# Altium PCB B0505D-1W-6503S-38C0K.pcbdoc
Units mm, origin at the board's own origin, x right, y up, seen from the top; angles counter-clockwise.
Board outline 33 x 16 mm, 2 copper layers (Top Layer, Bottom Layer), stack 0.78 mm thick; 15 components, 9 nets, 38 pads, 14 vias.
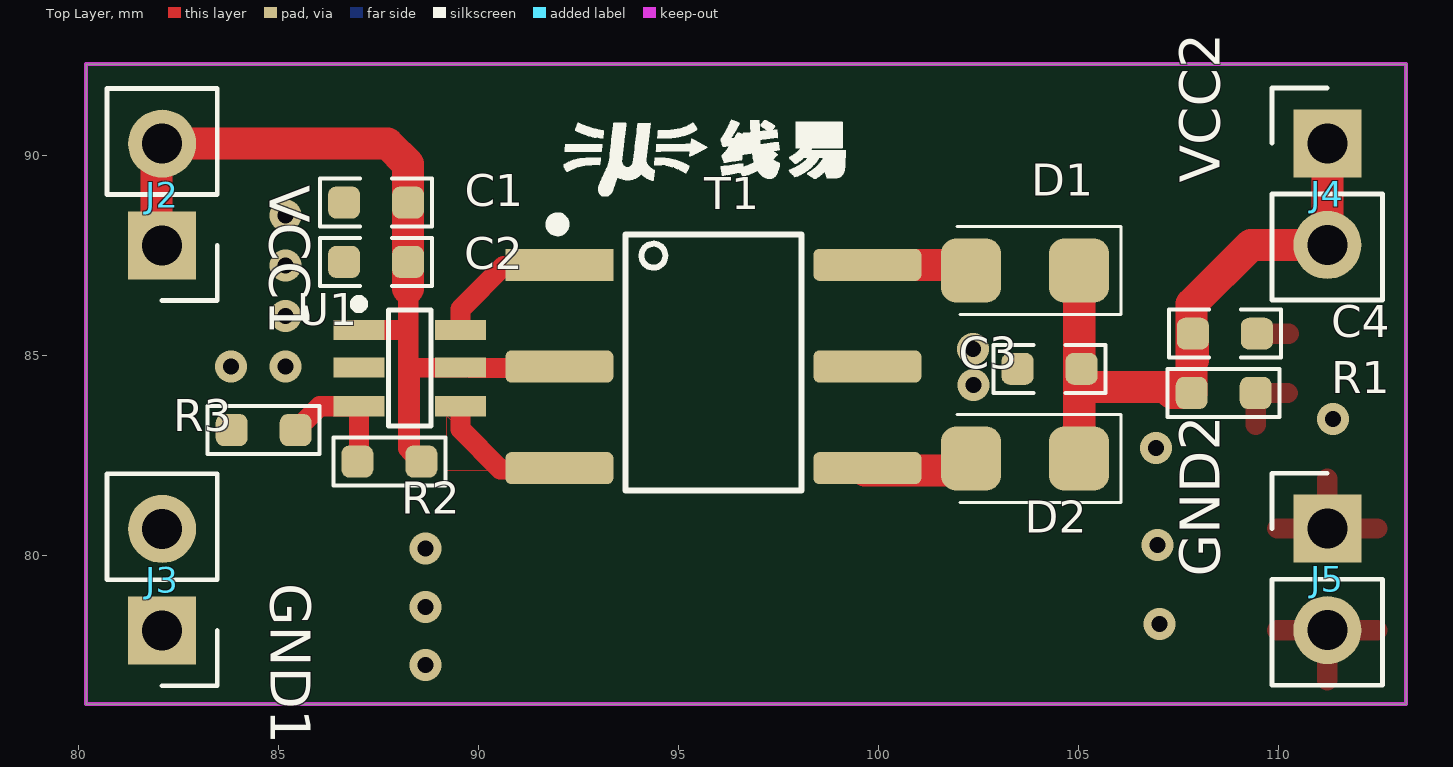
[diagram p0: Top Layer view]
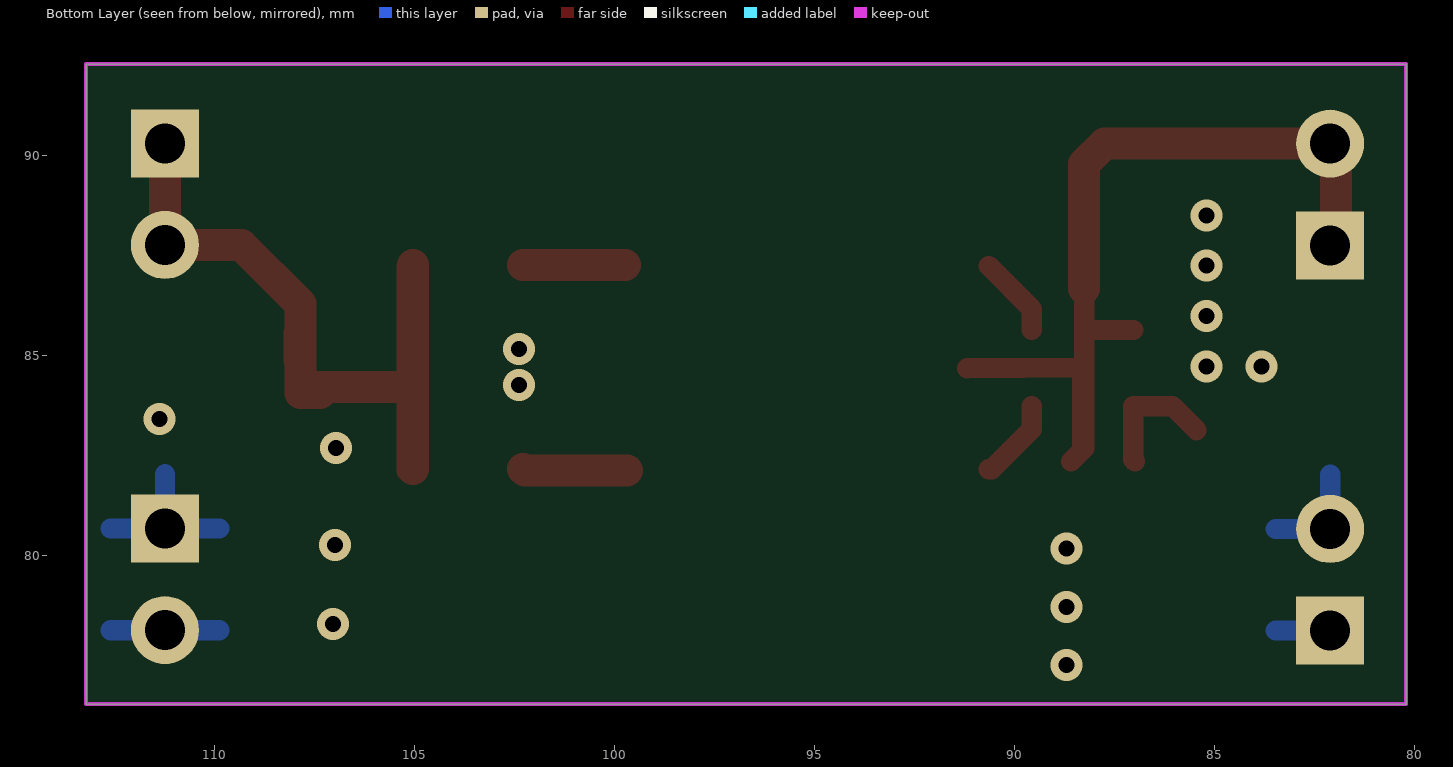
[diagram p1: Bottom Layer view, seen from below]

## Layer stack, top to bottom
Top Solder Mask Layer: solder mask 0.01, Dk 0
Top Layer: signal copper 0.035
dielectric 1: surface 0.71, FR4, Dk 4.5
Bottom Layer: signal copper 0.035
Bottom Solder Mask Layer: solder mask 0.01, Dk 0

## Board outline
80.2,92.284 113.2,92.284 113.2,76.284 80.2,76.284

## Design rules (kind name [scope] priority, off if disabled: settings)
BoardOutlineClearance default [All] p0: genericclearance=0.254 ignorepadtopadclearanceinfootprint=FALSE except(0: Arc-SplitContinuation Track-SplitContinuation SMDPad-SplitContinuation THPad-SplitContinuation Via-SplitContinuation Fill-SplitContinuation Poly-SplitContinuation Region-SplitContinuation Text-SplitContinuation)
BoardOutlineClearance safeClearance [All] p0: genericclearance=0.254 ignorepadtopadclearanceinfootprint=FALSE except(0: Arc-SplitContinuation Track-SplitContinuation SMDPad-SplitContinuation THPad-SplitContinuation Via-SplitContinuation Fill-SplitContinuation Poly-SplitContinuation Region-SplitContinuation Text-SplitContinuation)
BoardOutlineClearance otherClearance [All] p0: genericclearance=0.254 ignorepadtopadclearanceinfootprint=FALSE except(0: Arc-SplitContinuation Track-SplitContinuation SMDPad-SplitContinuation THPad-SplitContinuation Via-SplitContinuation Fill-SplitContinuation Poly-SplitContinuation Region-SplitContinuation Text-SplitContinuation)
Clearance default [All] p1: gap=0.178 ignorepadtopadclearanceinfootprint=FALSE
Clearance safeClearance [All] p1: gap=0.178 ignorepadtopadclearanceinfootprint=FALSE
Clearance otherClearance [All] p1: gap=0.178 ignorepadtopadclearanceinfootprint=FALSE
DiffPairsRouting differentialPair [All] p1: maxuncoupledlength=10 minlimit=5 maxlimit=Infinity mostfreqgap=6 toplayer_minwidth=5 toplayer_prefwidth=100 toplayer_maxwidth=100 bottomlayer_minwidth=5 bottomlayer_prefwidth=100 bottomlayer_maxwidth=100
PasteMaskExpansion pasteMaskExpansion [All] p1: expansion=0
PlaneConnect innerPlane [All] p1: planeconnectstyle=Relief reliefexpansion=0.508 reliefentries=4 reliefconductorwidth=0.254 reliefairgap=0.254
PolygonConnect copper0 [All] p1: connectstyle=Relief reliefentries=4 reliefconductorwidth=0 polygonreliefangle="90 Angle" airgapwidth=0
PolygonConnect copper1 [All] p1: connectstyle=Relief reliefentries=4 reliefconductorwidth=20 polygonreliefangle="90 Angle" airgapwidth=15.748
PolygonConnect copper2 [All] p1: connectstyle=Relief reliefentries=4 reliefconductorwidth=20 polygonreliefangle="90 Angle" airgapwidth=20
RoutingVias viaSize [All] p1: viastyle="Through Hole" holewidth=24 minholewidth=11.811 maxholewidth=393.7 width=24 minwidth=11.811 maxwidth=393.7
SolderMaskExpansion solderMaskExpansion [All] p1: useseparateexpansions=TRUE expansion=2 expansionbottom=2
Width copperThickness1oz [All] p1: maxlimit=100 minlimit=5 preferedwidth=10

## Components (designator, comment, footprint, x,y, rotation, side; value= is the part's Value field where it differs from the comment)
C1 "10uF" C0603 87.45,88.824 r0 top
C2 "NC" C0603 87.45,87.338 r0 top
C3 "10uF" C0603 104.288,84.668 r0 top
C4 "100nF" C0603 108.67,85.544 r180 top
D1 "B5819WS" SOD-323_L1.8-W1.3-LS2.5-RD 103.674,87.124 r180 top
D2 "B5819WS" SOD-323_L1.8-W1.3-LS2.5-RD 103.674,82.424 r180 top
J2 "HX PZ2.54-1x2P ZZ" HDR-TH_2P-P2.54-V-M-3 82.1,87.754 r180 top
J3 "HX PZ2.54-1x2P ZZ" HDR-TH_2P-P2.54-V-M-3 82.1,78.124 r180 top
J4 "HX PZ2.54-1x2P ZZ" HDR-TH_2P-P2.54-V-M-3 111.23,90.304 r0 top
J5 "HX PZ2.54-1x2P ZZ" HDR-TH_2P-P2.54-V-M-3 111.23,80.674 r0 top
R1 "4.7kΩ" R0603 108.64,84.064 r0 top
R2 "R" MYLibrary:R0603 87.78,82.348 r0 top
R3 "R" MYLibrary:R0603 84.64,83.134 r180 top
T1 "CMT38C0K" "My Library:CMT38C0K" 95.882,84.724 r0 top
U1 "CMP6503S" SOT-23-5_L2.9-W1.6-P0.95-LS2.8-BR 88.29,84.698 r0 top

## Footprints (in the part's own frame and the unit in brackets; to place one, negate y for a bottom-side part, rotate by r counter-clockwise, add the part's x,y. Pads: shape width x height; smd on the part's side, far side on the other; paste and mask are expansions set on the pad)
C0603 [mm]
  rrect50% 0.8x0.8 smd: 1(-0.8,0) 2(0.8,0)
  silkscreen extent -1.4,-0.6 1.4,0.6
HDR-TH_2P-P2.54-V-M-3 [mm]
  rect 1.7x1.7 hole 1: 1(0,0)
  round 1.7 hole 1: 2(0,-2.54)
  silkscreen extent -1.38,-3.92 1.38,1.38
"My Library:CMT38C0K" [mm]
  rect 2.7x0.8 smd: 1(-3.85,2.54)
  rrect37% 2.7x0.8 smd: 2(-3.85,0) 3(-3.85,-2.54) 4(3.85,-2.54) 5(3.85,0) 6(3.85,2.54)
  silkscreen extent -4.05,-3.1 2.2,3.71
MYLibrary:R0603 [mm]
  rrect50% 0.8x0.8 smd: 1(-0.8,0) 2(0.8,0)
  silkscreen extent -1.4,-0.6 1.4,0.6
R0603 [mm]
  rrect50% 0.8x0.8 smd: 1(-0.8,0) 2(0.8,0)
  silkscreen extent -1.4,-0.6 1.4,0.6
SOD-323_L1.8-W1.3-LS2.5-RD [mm]
  rrect50% 1.5x1.6 smd: 1(-1.35,0) 2(1.35,0)
  silkscreen extent -2.4,-1.1 1.7,1.1
SOT-23-5_L2.9-W1.6-P0.95-LS2.8-BR [mil]
  rect 50x20 smd: 1(-50,37) 2(-50,0) 3(-50,-38) 4(50,-38) 5(50,0) 6(50,37)
  silkscreen extent -54,-58 21,66

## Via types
v1: diameter 0.8, hole 0.4, Top Layer to Bottom Layer, 14 vias

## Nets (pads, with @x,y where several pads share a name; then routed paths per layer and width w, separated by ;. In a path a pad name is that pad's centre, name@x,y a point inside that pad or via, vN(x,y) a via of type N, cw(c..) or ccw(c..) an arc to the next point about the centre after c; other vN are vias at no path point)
$1N5: R2.1 R3.1 U1.3 | length 3.2
  Top Layer w0.508: R3.1 86.039,83.732 U1.3 87.02,82.388 R2.1
$1N6: D2.2 T1.4 | length 2.6
  Top Layer w0.8: T1.4@99.672,82.124 102.234,82.124 D2.2@102.274,82.164
$1N7: T1.3 U1.4 | length 2.1
  Top Layer w0.508: U1.4 89.56,83.154 90.556,82.158 90.636,82.158
$1N8: T1.1 U1.6 | length 2
  Top Layer w0.508: U1.6 89.56,86.162 90.636,87.238
$1N11: D1.2 T1.6 | length 2.5
  Top Layer w0.8: T1.6 D1.2@102.274,87.264
GND1: C1.1 C2.1 J3.1 J3.2 R3.2 U1.2
  other v1: 88.69,77.259 88.69,78.716 88.69,80.174 83.82,84.724 85.19,84.724 85.19,85.984 85.19,87.244 85.19,88.504
GND2: C3.1 C4.1 J5.1 J5.2 R1.2 T1.5
  other v1: 107.03,78.284 106.98,80.264 106.95,82.684 111.37,83.414 102.383,84.264 102.374,85.164
VCC1: C1.2 C2.2 J2.1 J2.2 R2.2 U1.1 U1.5 | length 22.5
  Top Layer w0.508: U1.1 88.19,85.637 88.25,85.698 ; 88.25,86.674 88.25,85.698 ; R2.2 R2.2@88.296,82.632 ; 91.178,84.683 88.296,84.698 R2.2@88.296,82.632 ; 88.25,85.698 88.25,82.678 R2.2@88.296,82.632
  Top Layer w0.8: J2.1@81.955,87.984 81.955,90.149 J2.2 87.74,90.294 88.25,89.784 C1.2 C2.2 88.25,86.674
VCC2: C3.2 C4.2 D1.1 D2.1 J4.1 J4.2 R1.1 | length 23.2
  Top Layer w0.6: D2.1@105.14,82.128 105.14,84.214 D1.1@105.14,87.208
  Top Layer w0.8: D2.1@105.024,82.164 D1.1@105.024,87.264 ; 105.088,84.214 105.14,84.214 107.2,84.214 ; C4.2 107.87,84.884 107.84,84.854 ; J4.1 J4.2 109.32,87.764 107.84,86.284 107.84,84.854 ; 107.2,84.214 107.35,84.064 R1.1 ; 107.2,84.214 107.69,84.214 R1.1 ; R1.1 107.84,84.854
pads on no net: T1.2

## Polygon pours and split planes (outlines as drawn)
GND1 on Top Layer (solid, remove dead copper, pour order 2): 86.995,89.129 86.995,82.129 89.2,82.129 89.2,76.304 76.32,76.304 76.32,84.104 78.62,84.104 80.72,86.204 80.72,89.129
GND1 on Top Layer (solid, remove dead copper, pour order 2): 89.2,82.129 90.74,82.129 89.2,83.495
GND1 on Bottom Layer (solid, remove dead copper, pour order 12): 91.9,76.284 76.2,76.284 76.2,92.284 91.9,92.284
GND2 on Top Layer (solid, remove dead copper, pour order 6): 103.888,83.768 102.024,83.768 102.024,83.764 101.738,84.068 99.238,84.068 99.188,85.268 101.688,85.268 101.924,85.664 101.924,85.668 103.888,85.668
GND2 on Top Layer (solid, remove dead copper, pour order 8): 113.324,76.2 106.27,76.25 106.3,76.254 106.279,79.934 106.279,83.33 108.754,83.33 108.954,83.63 108.954,86.16 113.324,86.16
GND2 on Bottom Layer (solid, remove dead copper, pour order 18): 113.225,76.299 96.975,76.351 96.975,92.351 113.225,92.299

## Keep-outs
Board Outline Layer:
  the board outline again, w0.1

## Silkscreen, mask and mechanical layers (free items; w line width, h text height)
Top Silkscreen Layer:
  drawing of 9 lines, arcs and shapes, not listed
  text "VCC2" at 108.54,89.324 h1 r90
  text "VCC1" at 84.79,89.254 h1 r270
  text "GND2" at 108.54,79.464 h1 r90
  text "GND1" at 84.81,79.304 h1 r270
